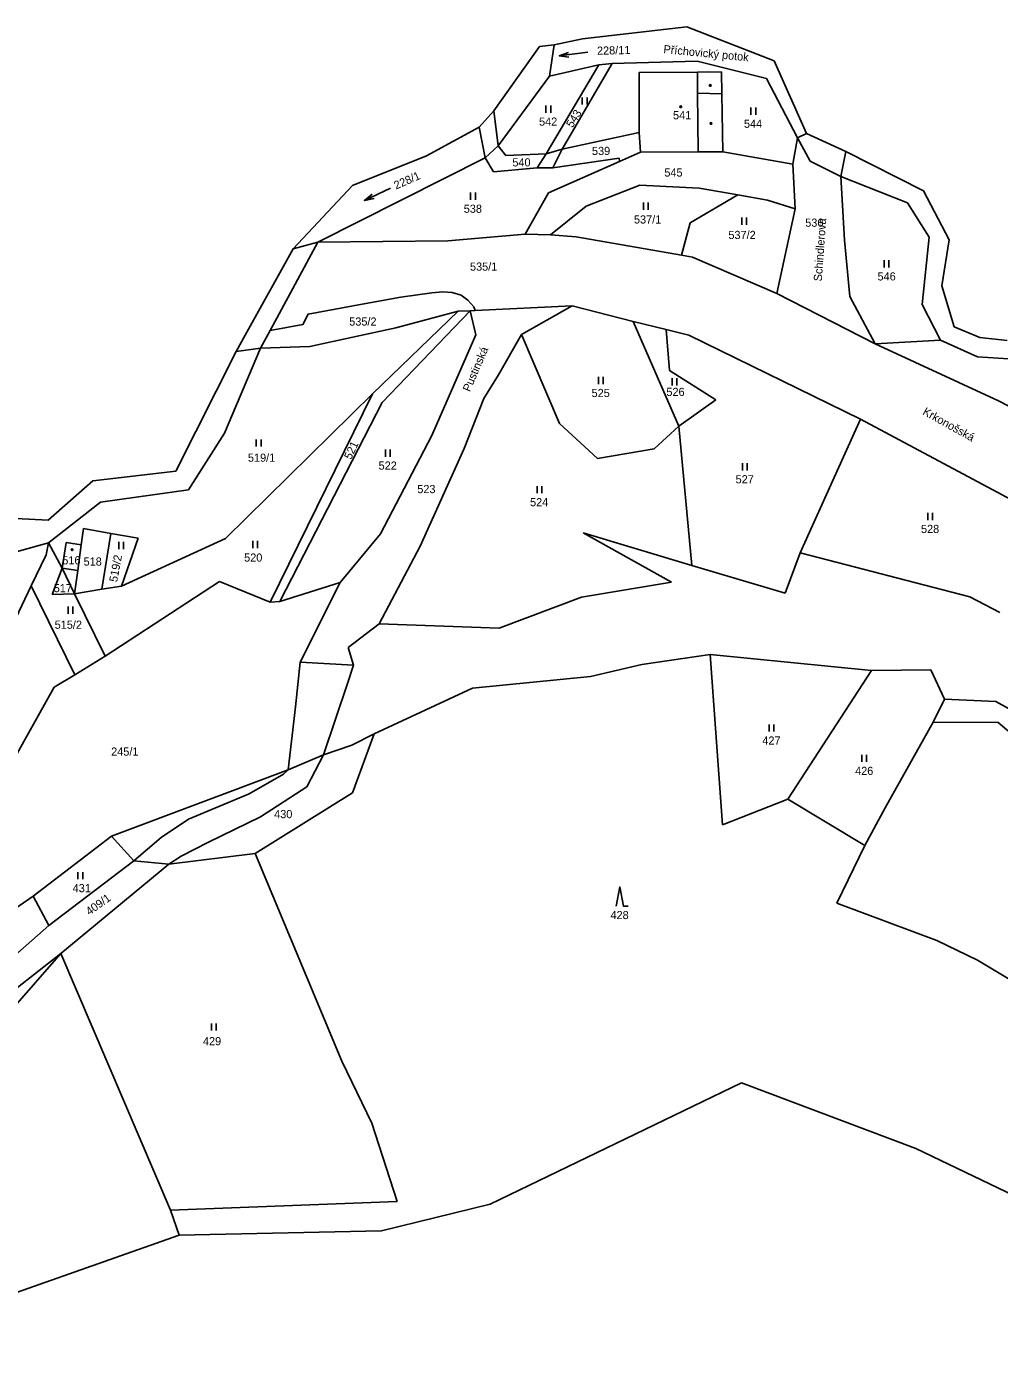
# Model space of a CAD drawing. Extents: x -670359 to -668019, y -978807 to -976674.
# Drawn here: x -668600.1 to -668397.5, y -976954.1 to -976674.2 of the extents above; entities that cross this region are included whole.
import ezdxf

# ---------------------------------------------------------------- set-up
doc = ezdxf.new("R2010")
doc.units = 0
for name, color, linetype in [('Hranice kat_území', 7, 'Continuous'), ('Hranice parcel', 7, 'Continuous'), ('Parcelní čísla', 7, 'Continuous'), ('Pop  PČ popisy', 7, 'Continuous'), ('Vnitřní kresba', 7, 'Continuous'), ('Značky budov', 7, 'Continuous'), ('Značky kultur', 7, 'Continuous')]:
    doc.layers.add(name, color=color, linetype=linetype)

msp = doc.modelspace()

# ---------------------------------------------------------------- linework, layer by layer
at = {"layer": 'Hranice kat_území'}
for points in [[(-668484.31, -976676.67), (-668462.6, -976674.19)], [(-668462.6, -976674.19), (-668444.37, -976681.25)], [(-668490.22, -976677.95), (-668484.31, -976676.67)], [(-668502.84, -976691.69), (-668493.32, -976678.28)], [(-668493.32, -976678.28), (-668490.22, -976677.95)], [(-668444.37, -976681.25), (-668437.68, -976696.39)], [(-668505.86, -976695.07), (-668502.84, -976691.69)], [(-668516.81, -976701.07), (-668505.86, -976695.07)], [(-668437.68, -976696.39), (-668429.46, -976700.18)], [(-668532.26, -976707.23), (-668516.81, -976701.07)], [(-668429.46, -976700.18), (-668413.29, -976708.34)], [(-668544.65, -976720.44), (-668532.26, -976707.23)], [(-668413.29, -976708.34), (-668407.93, -976718.55)], [(-668407.93, -976718.55), (-668409.48, -976728.13)], [(-668554.62, -976738.45), (-668544.65, -976720.44)], [(-668409.48, -976728.13), (-668406.87, -976736.71)], [(-668556.49, -976741.83), (-668554.62, -976738.45)], [(-668406.87, -976736.71), (-668401.56, -976738.95)], [(-668401.56, -976738.95), (-668395.86, -976739.55)], [(-668569.04, -976766.79), (-668556.49, -976741.83)], [(-668586.39, -976768.77), (-668569.04, -976766.79)], [(-668595.66, -976776.99), (-668586.39, -976768.77)], [(-668605.09, -976776.47), (-668595.66, -976776.99)]]:
    msp.add_lwpolyline(points, dxfattribs=at)
at = {"layer": 'Hranice parcel'}
for p, q in [((-668599.21, -976790.69), (-668596.1, -976784.2)), ((-668603.76, -976800.19), (-668599.21, -976790.69)), ((-668599.21, -976790.69), (-668590.11, -976809.18)), ((-668590.11, -976809.18), (-668583.8, -976805.31)), ((-668590.11, -976809.18), (-668594.41, -976811.81))]:
    msp.add_line(p, q, dxfattribs=at)
for points in [[(-668490.22, -976677.95), (-668491.21, -976684.49)], [(-668480.92, -976682.1), (-668491.89, -976700.66)], [(-668491.21, -976684.49), (-668480.92, -976682.1)], [(-668478.13, -976681.81), (-668488.54, -976699.66)], [(-668480.92, -976682.1), (-668478.13, -976681.81)], [(-668460.46, -976681.36), (-668478.13, -976681.81)], [(-668445.98, -976684.97), (-668460.46, -976681.36)], [(-668501.9, -976698.99), (-668491.21, -976684.49)], [(-668472.53, -976683.7), (-668460.38, -976683.61)], [(-668472.49, -976696.17), (-668472.53, -976683.7)], [(-668460.38, -976683.61), (-668455.4, -976683.57)], [(-668455.4, -976683.57), (-668455.31, -976688.14)], [(-668439.51, -976697.31), (-668445.98, -976684.97)], [(-668455.31, -976688.14), (-668455.06, -976700.26)], [(-668488.54, -976699.66), (-668472.49, -976696.17)], [(-668472.49, -976696.17), (-668472.28, -976700.33)], [(-668504.61, -976701.45), (-668501.9, -976698.99)], [(-668501.9, -976698.99), (-668500.31, -976701)], [(-668491.89, -976700.66), (-668488.54, -976699.66)], [(-668488.54, -976699.66), (-668490.54, -976703.57)], [(-668440.53, -976702.81), (-668439.51, -976697.31)], [(-668439.51, -976697.31), (-668436.9, -976702.18)], [(-668539.45, -976719.02), (-668504.61, -976701.45)], [(-668504.61, -976701.45), (-668502.85, -976704.4)], [(-668500.31, -976701), (-668491.89, -976700.66)], [(-668476.59, -976702.24), (-668491.43, -976708.74)], [(-668490.54, -976703.57), (-668476.66, -976701.52)], [(-668476.66, -976701.52), (-668476.59, -976702.24)], [(-668472.28, -976700.33), (-668476.59, -976702.24)], [(-668460.21, -976700.25), (-668472.28, -976700.33)], [(-668455.06, -976700.26), (-668460.21, -976700.25)], [(-668455.06, -976700.26), (-668440.53, -976702.81)], [(-668436.9, -976702.18), (-668430.52, -976705.36)], [(-668502.85, -976704.4), (-668493.75, -976703.59)], [(-668493.75, -976703.59), (-668490.54, -976703.57)], [(-668440.53, -976702.81), (-668440.02, -976712.09)], [(-668430.52, -976705.36), (-668416.64, -976710.88)], [(-668430.52, -976705.36), (-668429.74, -976718.63)], [(-668472.36, -976707.18), (-668483.57, -976711.52)], [(-668460.05, -976707.79), (-668472.36, -976707.18)], [(-668460.05, -976707.79), (-668451.98, -976709.2)], [(-668491.43, -976708.74), (-668496.31, -976717.38)], [(-668451.98, -976709.2), (-668461.88, -976715.02)], [(-668445.77, -976710.29), (-668451.98, -976709.2)], [(-668440.02, -976712.09), (-668445.77, -976710.29)], [(-668416.64, -976710.88), (-668412.09, -976718.03)], [(-668483.57, -976711.52), (-668490.98, -976717.54)], [(-668440.02, -976712.09), (-668443.86, -976729.72)], [(-668461.88, -976715.02), (-668463.68, -976721.78)], [(-668549.42, -976737.48), (-668539.45, -976719.02)], [(-668539.45, -976719.02), (-668512.37, -976718.8)], [(-668512.37, -976718.8), (-668496.31, -976717.38)], [(-668496.31, -976717.38), (-668490.98, -976717.54)], [(-668490.98, -976717.54), (-668485.62, -976717.93)], [(-668485.62, -976717.93), (-668463.68, -976721.78)], [(-668429.74, -976718.63), (-668428.65, -976730.34)], [(-668412.09, -976718.03), (-668413.57, -976732.03)], [(-668461.41, -976722.18), (-668463.68, -976721.78)], [(-668461.41, -976722.18), (-668443.86, -976729.72)], [(-668549.42, -976737.48), (-668542.6, -976736.2), (-668541.51, -976734.05), (-668530.23, -976731.96), (-668522.19, -976730.54), (-668515.7, -976729.62), (-668513.42, -976729.41), (-668511.52, -976729.54), (-668509.6, -976730.13), (-668508.26, -976731.14), (-668507.01, -976732.52), (-668506.69, -976733.28)], [(-668443.86, -976729.72), (-668423.33, -976740.24)], [(-668428.65, -976730.34), (-668423.33, -976740.24)], [(-668528.08, -976750.67), (-668510.21, -976733.43)], [(-668507.73, -976733.33), (-668526.1, -976752.45)], [(-668523.2, -976736.92), (-668510.21, -976733.43)], [(-668510.21, -976733.43), (-668507.73, -976733.33)], [(-668506.69, -976733.28), (-668507.73, -976733.33)], [(-668507.73, -976733.33), (-668506.54, -976738.35)], [(-668486.49, -976732.35), (-668506.69, -976733.28)], [(-668497.05, -976738.3), (-668486.49, -976732.35)], [(-668473.75, -976735.57), (-668486.49, -976732.35)], [(-668413.57, -976732.03), (-668409.72, -976739.5)], [(-668466.88, -976737.25), (-668473.75, -976735.57)], [(-668464.25, -976757.41), (-668473.75, -976735.57)], [(-668551.4, -976741.14), (-668549.42, -976737.48)], [(-668541.15, -976740.77), (-668523.2, -976736.92)], [(-668506.54, -976738.35), (-668515.73, -976759.37)], [(-668501.87, -976746.7), (-668497.05, -976738.3)], [(-668489.11, -976756.85), (-668497.05, -976738.3)], [(-668462.17, -976738.44), (-668466.88, -976737.25)], [(-668466.21, -976745.79), (-668466.88, -976737.25)], [(-668426.4, -976755.93), (-668462.17, -976738.44)], [(-668558.94, -976758.84), (-668551.4, -976741.14)], [(-668551.4, -976741.14), (-668541.15, -976740.77)], [(-668409.72, -976739.5), (-668423.33, -976740.24)], [(-668423.33, -976740.24), (-668397.66, -976752.14)], [(-668409.72, -976739.5), (-668402.02, -976742.95)], [(-668402.02, -976742.95), (-668395.53, -976743.38)], [(-668504.88, -976751.61), (-668501.87, -976746.7)], [(-668456.54, -976751.91), (-668466.21, -976745.79)], [(-668558.71, -976780.8), (-668528.08, -976750.67)], [(-668528.08, -976750.67), (-668549.39, -976794.07)], [(-668526.1, -976752.45), (-668547.4, -976793.93)], [(-668509, -976762.03), (-668504.88, -976751.61)], [(-668464.25, -976757.41), (-668456.54, -976751.91)], [(-668397.66, -976752.14), (-668371.58, -976765.6)], [(-668481.24, -976764.13), (-668489.11, -976756.85)], [(-668464.25, -976757.41), (-668469.38, -976762.14)], [(-668464.25, -976757.41), (-668461.53, -976786.4)], [(-668426.4, -976755.93), (-668439.01, -976783.79)], [(-668385.67, -976777.65), (-668426.4, -976755.93)], [(-668566.42, -976770.69), (-668558.94, -976758.84)], [(-668515.73, -976759.37), (-668526.43, -976779.83)], [(-668518.18, -976782.4), (-668509, -976762.03)], [(-668469.38, -976762.14), (-668481.24, -976764.13)], [(-668584.78, -976773.23), (-668566.42, -976770.69)], [(-668595.6, -976781.67), (-668584.78, -976773.23)], [(-668588.79, -976782.1), (-668588.32, -976778.7)], [(-668588.32, -976778.7), (-668582.62, -976779.73)], [(-668582.62, -976779.73), (-668584.5, -976791.33)], [(-668582.62, -976779.73), (-668576.92, -976780.7)], [(-668576.92, -976780.7), (-668580.37, -976790.71)], [(-668580.37, -976790.71), (-668558.71, -976780.8)], [(-668526.43, -976779.83), (-668534.81, -976789.95)], [(-668484.16, -976779.64), (-668465.76, -976789.91)], [(-668484.16, -976779.64), (-668461.53, -976786.4)], [(-668602.32, -976783.56), (-668595.6, -976781.67)], [(-668595.6, -976781.67), (-668596.1, -976784.2)], [(-668595.6, -976781.67), (-668592.77, -976786.96)], [(-668592.77, -976786.96), (-668591.95, -976781.61)], [(-668591.95, -976781.61), (-668588.79, -976782.1)], [(-668588.79, -976782.1), (-668589.52, -976787.45)], [(-668526.67, -976798.6), (-668518.18, -976782.4)], [(-668442.08, -976792.21), (-668439.01, -976783.79)], [(-668403.65, -976792.99), (-668439.01, -976783.79)], [(-668442.08, -976792.21), (-668461.53, -976786.4)], [(-668592.77, -976786.96), (-668594.86, -976792.48)], [(-668590.21, -976792.31), (-668592.77, -976786.96)], [(-668589.52, -976787.45), (-668590.21, -976792.31)], [(-668584.5, -976791.33), (-668590.21, -976792.31)], [(-668584.5, -976791.33), (-668580.37, -976790.71)], [(-668560, -976789.75), (-668583.8, -976805.31)], [(-668549.39, -976794.07), (-668560, -976789.75)], [(-668534.81, -976789.95), (-668547.4, -976793.93)], [(-668543.13, -976806.55), (-668534.81, -976789.95)], [(-668465.76, -976789.91), (-668484.51, -976793.05)], [(-668594.86, -976792.48), (-668590.21, -976792.31)], [(-668590.21, -976792.31), (-668583.8, -976805.31)], [(-668547.4, -976793.93), (-668549.39, -976794.07)], [(-668484.51, -976793.05), (-668501.7, -976799.47)], [(-668397.37, -976796.2), (-668403.65, -976792.99)], [(-668526.67, -976798.6), (-668533.16, -976803.48)], [(-668501.7, -976799.47), (-668526.67, -976798.6)], [(-668533.16, -976803.48), (-668532.03, -976807.22)], [(-668457.71, -976804.98), (-668472, -976807.06)], [(-668424.1, -976808.31), (-668457.71, -976804.98)], [(-668457.71, -976804.98), (-668455.13, -976840.43)], [(-668532.03, -976807.22), (-668543.13, -976806.55)], [(-668482.66, -976809.54), (-668472, -976807.06)], [(-668424.1, -976808.31), (-668441.52, -976835.12)], [(-668411.75, -976808.15), (-668424.1, -976808.31)], [(-668408.89, -976814.25), (-668411.75, -976808.15)], [(-668594.41, -976811.81), (-668606.48, -976833.3)], [(-668507.25, -976812), (-668482.66, -976809.54)], [(-668507.25, -976812), (-668527.73, -976821.53)], [(-668408.89, -976814.25), (-668411.27, -976819.09)], [(-668398.2, -976814.79), (-668408.89, -976814.25)], [(-668352.59, -976840.01), (-668398.2, -976814.79)], [(-668411.27, -976819.09), (-668421.28, -976836.9)], [(-668411.27, -976819.09), (-668397.73, -976819.17)], [(-668397.73, -976819.17), (-668380.39, -976833.81)], [(-668527.73, -976821.53), (-668532.37, -976823.87)], [(-668532.29, -976833.81), (-668527.73, -976821.53)], [(-668532.37, -976823.87), (-668538.32, -976825.9)], [(-668545.64, -976829.01), (-668538.32, -976825.9)], [(-668545.64, -976829.01), (-668582.51, -976842.83)], [(-668552.56, -976846.43), (-668532.29, -976833.81)], [(-668455.13, -976840.43), (-668441.52, -976835.12)], [(-668441.52, -976835.12), (-668425.51, -976844.75)], [(-668421.28, -976836.9), (-668425.51, -976844.75)], [(-668582.51, -976842.83), (-668598.78, -976855.32)], [(-668577.81, -976847.94), (-668582.51, -976842.83)], [(-668425.51, -976844.75), (-668431.31, -976856.8)], [(-668577.81, -976847.94), (-668595.53, -976861.42)], [(-668570.53, -976848.69), (-668577.81, -976847.94)], [(-668552.56, -976846.43), (-668570.53, -976848.69)], [(-668534.48, -976889.7), (-668552.56, -976846.43)], [(-668593.01, -976867.25), (-668570.53, -976848.69)], [(-668598.78, -976855.32), (-668621.49, -976870.96)], [(-668595.53, -976861.42), (-668598.78, -976855.32)], [(-668431.31, -976856.8), (-668410.51, -976864.55)], [(-668595.53, -976861.42), (-668608.05, -976872.43)], [(-668410.51, -976864.55), (-668402.03, -976868.63)], [(-668593.01, -976867.25), (-668648.72, -976930.95)], [(-668607.59, -976878.65), (-668593.01, -976867.25)], [(-668570.17, -976920.76), (-668593.01, -976867.25)], [(-668402.03, -976868.63), (-668393.67, -976873.69)], [(-668528.24, -976902.64), (-668534.48, -976889.7)], [(-668451.22, -976894.25), (-668503.6, -976919.48)], [(-668414.9, -976907.91), (-668451.22, -976894.25)], [(-668522.96, -976918.93), (-668528.24, -976902.64)], [(-668378.82, -976925.21), (-668414.9, -976907.91)], [(-668570.17, -976920.76), (-668522.96, -976918.93)], [(-668568.35, -976926), (-668570.17, -976920.76)], [(-668503.6, -976919.48), (-668526.2, -976925.04)], [(-668648.24, -976954.09), (-668568.35, -976926)], [(-668526.2, -976925.04), (-668568.35, -976926)]]:
    msp.add_lwpolyline(points, dxfattribs=at)
at = {"layer": 'Vnitřní kresba'}
for points in [[(-668460.38, -976683.61), (-668460.39, -976688.04)], [(-668460.39, -976688.04), (-668460.21, -976700.25)], [(-668460.39, -976688.04), (-668455.31, -976688.14)], [(-668501.9, -976698.99), (-668502.84, -976691.69)], [(-668504.61, -976701.45), (-668505.86, -976695.07)], [(-668439.51, -976697.31), (-668437.68, -976696.39)], [(-668491.89, -976700.66), (-668493.75, -976703.59)], [(-668430.52, -976705.36), (-668429.46, -976700.18)], [(-668539.45, -976719.02), (-668544.65, -976720.44)], [(-668551.4, -976741.14), (-668556.49, -976741.83)], [(-668592.77, -976786.96), (-668589.52, -976787.45)], [(-668543.13, -976806.55), (-668544.17, -976815.9)], [(-668532.03, -976807.22), (-668533.31, -976811.02)], [(-668533.31, -976811.02), (-668538.32, -976825.9)], [(-668544.17, -976815.9), (-668545.64, -976829.01)], [(-668538.32, -976825.9), (-668541.77, -976832.57)], [(-668553.78, -976834.01), (-668546.62, -976829.88)], [(-668546.62, -976829.88), (-668545.64, -976829.01)], [(-668566.4, -976839.25), (-668553.78, -976834.01)], [(-668541.77, -976832.57), (-668551.43, -976838.81)], [(-668572.14, -976843.12), (-668566.4, -976839.25)], [(-668551.43, -976838.81), (-668562.28, -976844.09)], [(-668577.81, -976847.94), (-668572.14, -976843.12)], [(-668562.28, -976844.09), (-668567.93, -976846.98)], [(-668567.93, -976846.98), (-668570.53, -976848.69)]]:
    msp.add_lwpolyline(points, dxfattribs=at)
at = {"layer": 'Značky budov'}
for centre in [(-668463.86, -976690.85), (-668590.68, -976783.13)]:
    msp.add_circle(centre, 0.175, dxfattribs=at)
at = {"layer": 'Značky kultur'}
for p, q in [((-668483.25, -976679.48), (-668489.19, -976680.26)), ((-668491.96, -976690.58), (-668491.96, -976692.08)), ((-668490.96, -976692.08), (-668490.96, -976690.58)), ((-668484.39, -976688.9), (-668484.39, -976690.4)), ((-668483.39, -976690.4), (-668483.39, -976688.9)), ((-668449.23, -976691.02), (-668449.23, -976692.52)), ((-668448.23, -976692.52), (-668448.23, -976691.02)), ((-668524.37, -976707.77), (-668529.77, -976710.37)), ((-668507.65, -976708.73), (-668507.65, -976710.23)), ((-668506.65, -976710.23), (-668506.65, -976708.73)), ((-668471.64, -976710.82), (-668471.64, -976712.32)), ((-668470.64, -976712.32), (-668470.64, -976710.82)), ((-668451.15, -976713.94), (-668451.15, -976715.44)), ((-668450.15, -976715.44), (-668450.15, -976713.94)), ((-668421.47, -976722.83), (-668421.47, -976724.33)), ((-668420.47, -976724.33), (-668420.47, -976722.83)), ((-668481.01, -976747.13), (-668481.01, -976748.63)), ((-668480.01, -976748.63), (-668480.01, -976747.13)), ((-668465.67, -976747.4), (-668465.67, -976748.9)), ((-668464.67, -976748.9), (-668464.67, -976747.4)), ((-668552.32, -976760.16), (-668552.32, -976761.66)), ((-668551.32, -976761.66), (-668551.32, -976760.16)), ((-668525.39, -976762.25), (-668525.39, -976763.75)), ((-668524.39, -976763.75), (-668524.39, -976762.25)), ((-668451, -976765.11), (-668451, -976766.61)), ((-668450, -976766.61), (-668450, -976765.11)), ((-668493.8, -976769.88), (-668493.8, -976771.38)), ((-668492.8, -976771.38), (-668492.8, -976769.88)), ((-668412.37, -976775.46), (-668412.37, -976776.96)), ((-668411.37, -976776.96), (-668411.37, -976775.46)), ((-668580.95, -976781.5), (-668580.95, -976783)), ((-668579.95, -976783), (-668579.95, -976781.5)), ((-668553.04, -976781.3), (-668553.04, -976782.8)), ((-668552.04, -976782.8), (-668552.04, -976781.3)), ((-668591.53, -976794.97), (-668591.53, -976796.47)), ((-668590.53, -976796.47), (-668590.53, -976794.97)), ((-668445.43, -976819.55), (-668445.43, -976821.05)), ((-668444.43, -976821.05), (-668444.43, -976819.55)), ((-668426.14, -976825.87), (-668426.14, -976827.37)), ((-668425.14, -976827.37), (-668425.14, -976825.87)), ((-668589.46, -976850.3), (-668589.46, -976851.8)), ((-668588.46, -976851.8), (-668588.46, -976850.3)), ((-668561.64, -976881.84), (-668561.64, -976883.34)), ((-668560.64, -976883.34), (-668560.64, -976881.84))]:
    msp.add_line(p, q, dxfattribs=at)
for points in [[(-668487.15, -976680.5), (-668489.19, -976680.26), (-668487.28, -976679.51)], [(-668527.76, -976709.95), (-668529.77, -976710.37), (-668528.19, -976709.05)], [(-668477.32, -976857.41), (-668476.57, -976853.41), (-668475.82, -976857.41), (-668474.82, -976857.41)]]:
    msp.add_lwpolyline(points, dxfattribs=at)
for centre in [(-668457.71, -976686.4), (-668463.86, -976690.85), (-668457.55, -976694.31), (-668590.68, -976783.13)]:
    msp.add_circle(centre, 0.175, dxfattribs=at)

# ---------------------------------------------------------------- texts
at = {"layer": 'Parcelní čísla'}
for s, rotation, p in [('228/11', 1.3751, (-668481.29, -976680.01)), ('543', 58.4958, (-668486.42, -976695.34)), ('228/1', 23.6632, (-668523.18, -976708.1)), ('521', 64.8851, (-668532.56, -976764.48)), ('519/2', 79.4874, (-668581.31, -976789.97)), ('409/1', 35.6662, (-668587.08, -976859.4))]:
    msp.add_text(s, height=1.7, rotation=rotation, dxfattribs=at).set_placement(p)
for s, p in [('542', (-668493.39, -976694.78)), ('541', (-668465.47, -976693.45)), ('544', (-668450.69, -976695.22)), ('539', (-668482.36, -976700.89)), ('540', (-668498.95, -976703.27)), ('545', (-668467.28, -976705.39)), ('538', (-668509.08, -976712.93)), ('537/1', (-668473.61, -976715.17)), ('537/2', (-668453.93, -976718.4)), ('536', (-668437.92, -976715.84)), ('535/1', (-668507.78, -976724.99)), ('546', (-668422.86, -976727.03)), ('535/2', (-668532.94, -976736.44)), ('525', (-668482.44, -976751.33)), ('526', (-668466.85, -976751.1)), ('519/1', (-668554.05, -976764.81)), ('522', (-668526.82, -976766.45)), ('523', (-668518.76, -976771.35)), ('527', (-668452.43, -976769.31)), ('524', (-668495.26, -976774.08)), ('528', (-668413.8, -976779.66)), ('516', (-668592.73, -976786.19)), ('518', (-668588.29, -976786.45)), ('520', (-668554.84, -976785.62)), ('517', (-668594.52, -976792)), ('515/2', (-668594.32, -976799.61)), ('427', (-668446.86, -976823.75)), ('245/1', (-668582.55, -976826.05)), ('426', (-668427.53, -976830.07)), ('430', (-668548.59, -976839.08)), ('431', (-668590.57, -976854.5)), ('428', (-668478.5, -976860.11)), ('429', (-668563.42, -976886.39))]:
    msp.add_text(s, height=1.7, dxfattribs=at).set_placement(p)
at = {"layer": 'Pop  PČ popisy'}
for s, rotation, p in [('Příchovický potok', 354.4328, (-668467.52, -976679.65)), ('Schindlerova', 85.9341, (-668434.48, -976727.25)), ('Pustinská', 66.8195, (-668507.8, -976750.36)), ('Krkonošská', 330.8899, (-668413.6, -976754.87))]:
    msp.add_text(s, height=1.7, rotation=rotation, dxfattribs=at).set_placement(p)

doc.saveas('drawing.dxf')
